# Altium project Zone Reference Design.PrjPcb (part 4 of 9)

## Sheet DRV8x45S-Q1 and DRV81242-Q1.SchDoc
size 431 x 279 mm; Date: Not shown in title block; ApprovedBy: Not shown in title block; CheckedBy: Not shown in title block; Author: Not shown in title block; CompanyName: Not shown in title block; Engineer: Not shown in title block; Organization: Not shown in title block; Address1: Not shown in title block; Address2: Not shown in title block; Address3: Not shown in title block; Address4: Not shown in title block; DocumentNumber: 1; Revision: Use project parameter SCH_Rev; SheetNumber: 18; SheetTotal: 30; PageSetup: Record=PageOptions¦CenterHorizontal=True¦CenterVertical=True¦PrintScale=1.00¦XCorrection=1.00¦YCorrection=1.00¦PrintKind=0¦BorderSize=5000000¦LeftOffset=0¦BottomOffset=0¦Orientation=2¦PaperLength=1000¦PaperWidth=1000¦Scale=100¦PaperSource=15¦PrintQuality=600¦MediaType=1¦DitherType=10¦PaperKind=Letter¦PrintScaleMode=1
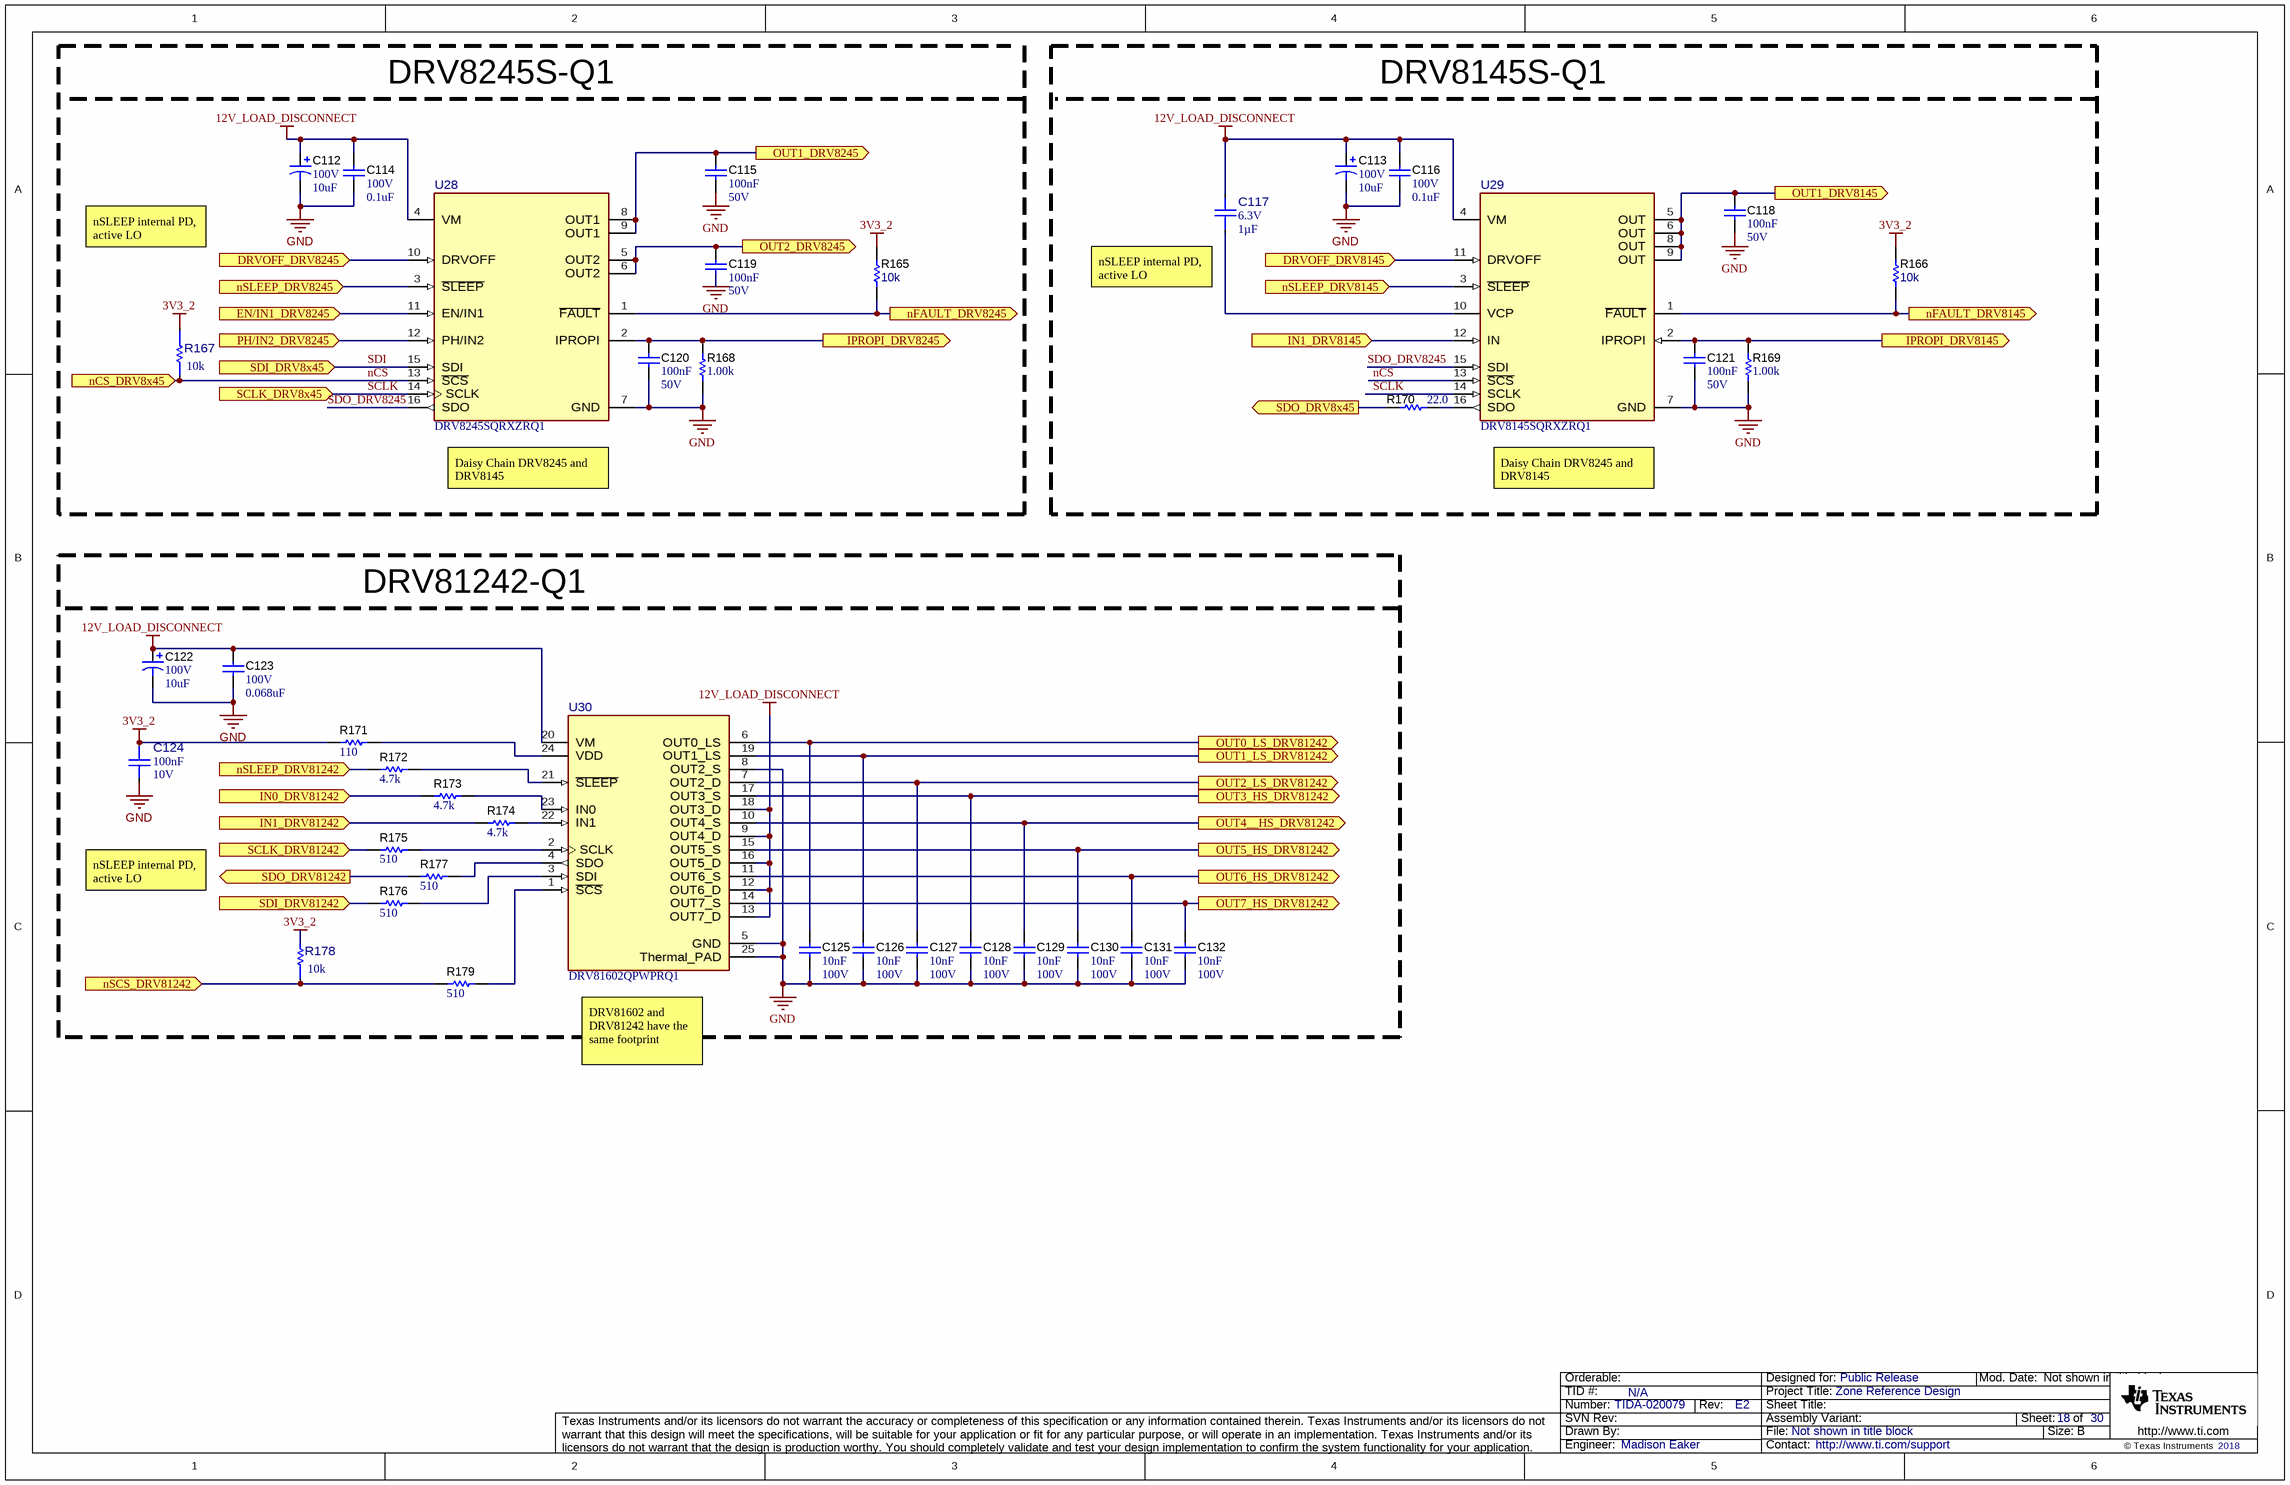
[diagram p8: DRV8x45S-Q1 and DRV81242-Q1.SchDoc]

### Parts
C112  VDC_V: 100V  ValueDisplayed: 10uF  [SM_RADIAL_E]  (hidden comment: EEE-2AA100UP)
C113  VDC_V: 100V  ValueDisplayed: 10uF  [SM_RADIAL_E]  (hidden comment: EEE-2AA100UP)
C114  VDC_V: 100V  ValueDisplayed: 0.1uF  [1206_180]  (hidden comment: C3216X7R2A104K160AA)
C115  Cap_F: 100nF  VDC_V: 50V  [0603]  (hidden comment: 885012206095)
C116  VDC_V: 100V  ValueDisplayed: 0.1uF  [1206_180]  (hidden comment: C3216X7R2A104K160AA)
C117  VDC_V: 6.3V  Cap_F: 1µF  [FP-C0603X105J9RACAUTO_0603-MFG]  (hidden comment: C0603X105J9RACAUTO)
C118  Cap_F: 100nF  VDC_V: 50V  [0603]  (hidden comment: 885012206095)
C119  Cap_F: 100nF  VDC_V: 50V  [0603]  (hidden comment: 885012206095)
C120  Cap_F: 100nF  VDC_V: 50V  [0603]  (hidden comment: 885012206095)
C121  Cap_F: 100nF  VDC_V: 50V  [0603]  (hidden comment: 885012206095)
C122  VDC_V: 100V  ValueDisplayed: 10uF  [SM_RADIAL_E]  (hidden comment: EEE-2AA100UP)
C123  VDC_V: 100V  ValueDisplayed: 0.068uF  [0603]  (hidden comment: CGA3E3X7S2A683K080AB)
C124  value 100nF  VDC_V: 10V  [FP-885012205018_0402-MFG]  (hidden comment: 885012205018)
C125  Cap_F: 10nF  VDC_V: 100V  [0603]  (hidden comment: CGA3E2X7R2A103K080AA)
C126  Cap_F: 10nF  VDC_V: 100V  [0603]  (hidden comment: CGA3E2X7R2A103K080AA)
C127  Cap_F: 10nF  VDC_V: 100V  [0603]  (hidden comment: CGA3E2X7R2A103K080AA)
C128  Cap_F: 10nF  VDC_V: 100V  [0603]  (hidden comment: CGA3E2X7R2A103K080AA)
C129  Cap_F: 10nF  VDC_V: 100V  [0603]  (hidden comment: CGA3E2X7R2A103K080AA)
C130  Cap_F: 10nF  VDC_V: 100V  [0603]  (hidden comment: CGA3E2X7R2A103K080AA)
C131  Cap_F: 10nF  VDC_V: 100V  [0603]  (hidden comment: CGA3E2X7R2A103K080AA)
C132  Cap_F: 10nF  VDC_V: 100V  [0603]  (hidden comment: CGA3E2X7R2A103K080AA)
R165  ValueDisplayed: 10k  [0603]  (hidden comment: RC0603JR-0710KL)
R166  ValueDisplayed: 10k  [0603]  (hidden comment: RC0603JR-0710KL)
R167  value 10k  [FP-RC0402JR-0710KL_0402-MFG]  (hidden comment: RC0402JR-0710KL)
R168  ValueDisplayed: 1.00k  [0603]  (hidden comment: CRCW06031K00FKEA)
R169  ValueDisplayed: 1.00k  [0603]  (hidden comment: CRCW06031K00FKEA)
R170  ValueDisplayed: 22.0  [0201]  (hidden comment: RC0201FR-0722RL)
R171  ValueDisplayed: 110  [0603]  (hidden comment: CRCW0603110RJNEA)
R172  ValueDisplayed: 4.7k  [0603]  (hidden comment: CRCW06034K70JNEA)
R173  ValueDisplayed: 4.7k  [0603]  (hidden comment: CRCW06034K70JNEA)
R174  ValueDisplayed: 4.7k  [0603]  (hidden comment: CRCW06034K70JNEA)
R175  ValueDisplayed: 510  [0603]  (hidden comment: CRCW0603510RJNEA)
R176  ValueDisplayed: 510  [0603]  (hidden comment: CRCW0603510RJNEA)
R177  ValueDisplayed: 510  [0603]  (hidden comment: CRCW0603510RJNEA)
R178  value 10k  [FP-RC0402JR-0710KL_0402-MFG]  (hidden comment: RC0402JR-0710KL)
R179  ValueDisplayed: 510  [0603]  (hidden comment: CRCW0603510RJNEA)
U28  DRV8245SQRXZRQ1  [RXZ0016A-MFG]
U29  DRV8145SQRXZRQ1  [RXZ0016A-MFG]
U30  DRV81602QPWPRQ1  [PWP0024T-MFG]

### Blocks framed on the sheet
DRV8145S-Q1: C113 C116-C118 C121 R166 R169 R170 U29

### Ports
DRVOFF_DRV8145 (in), DRVOFF_DRV8245 (in), EN/IN1_DRV8245 (in), IN0_DRV81242 (in), IN1_DRV8145 (in), IN1_DRV81242 (in), IPROPI_DRV8145 (out), IPROPI_DRV8245 (out), nCS_DRV8x45 (in), nFAULT_DRV8145 (out), nFAULT_DRV8245 (out), nSCS_DRV81242 (in), nSLEEP_DRV8145 (in), nSLEEP_DRV8245 (in), nSLEEP_DRV81242 (in), OUT0_LS_DRV81242 (out), OUT1_DRV8145 (out), OUT1_DRV8245 (out), OUT1_LS_DRV81242 (out), OUT2_DRV8245 (out), OUT2_LS_DRV81242 (out), OUT3_HS_DRV81242 (out), OUT4__HS_DRV81242 (out), OUT5_HS_DRV81242 (out), OUT6_HS_DRV81242 (out), OUT7_HS_DRV81242 (out), PH/IN2_DRV8245 (in), SCLK_DRV8x45 (in), SCLK_DRV81242 (in), SDI_DRV8x45 (in), SDI_DRV81242 (in), SDO_DRV8x45 (out), SDO_DRV81242 (out)

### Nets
3V3_2: C124.1 R165.2 R166.2 R167.1 R171.1 R178.1
12V_LOAD_DISCONNECT: C112.1(+) C113.1(+) C114.1 C116.1 C117.2 C122.1(+) C123.1 U28.4(VM) U29.4(VM) U30.9(OUT4_D) U30.12(OUT6_D) U30.13(OUT7_D) U30.16(OUT5_D) U30.18(OUT3_D) U30.20(VM)  [project net VS]
GND: C112.2(-) C113.2(-) C114.2 C115.1 C116.2 C118.1 C119.1 C120.1 C121.1 C122.2(-) C123.2 C124.2 C125.2 C126.2 C127.2 C128.2 C129.2 C130.2 C131.2 C132.2 R168.1 R169.1 U28.7(GND) U29.7(GND) U30.5(GND) U30.8(OUT2_S) U30.25(Thermal_PAD)
ADC4_AIN0: C121.2 R169.2 U29.2(IPROPI) ; port IPROPI_DRV8145
ADC4_AIN1: C120.2 R168.2 U28.2(IPROPI) ; port IPROPI_DRV8245
CS_LD_4: R178.2 R179.1 ; port nSCS_DRV81242
DRVOFF_DRV8145: U28.10(DRVOFF) U29.11(DRVOFF) ; port DRVOFF_DRV8245, port DRVOFF_DRV8145
EN/IN1_DRV8245: U28.11(EN/IN1) ; port EN/IN1_DRV8245
EPWM0_B: U28.12(PH/IN2) ; port PH/IN2_DRV8245
EPWM1_A: R173.1 ; port IN0_DRV81242
EPWM1_B: R174.1 ; port IN1_DRV81242
EPWM2_A: U29.12(IN) ; port IN1_DRV8145
nCS: R167.2 U28.13(~{SCS}) U29.13(~{SCS}) ; port nCS_DRV8x45
nFAULT_DRV8145: R165.1 R166.1 U28.1(~{FAULT}) U29.1(~{FAULT}) ; port nFAULT_DRV8245, port nFAULT_DRV8145
nSLEEP_DRV81242: R172.1 U28.3(~{SLEEP}) U29.3(~{SLEEP}) ; port nSLEEP_DRV8245, port nSLEEP_DRV8145, port nSLEEP_DRV81242
OUT0_LS_DRV81242: C125.1 U30.6(OUT0_LS) ; port OUT0_LS_DRV81242
OUT1_DRV8145: C118.2 U29.5(OUT) U29.6(OUT) U29.8(OUT) U29.9(OUT) ; port OUT1_DRV8145
OUT1_DRV8245: C115.2 U28.8(OUT1) U28.9(OUT1) ; port OUT1_DRV8245
OUT1_LS_DRV81242: C126.1 U30.19(OUT1_LS) ; port OUT1_LS_DRV81242
OUT2_DRV8245: C119.2 U28.5(OUT2) U28.6(OUT2) ; port OUT2_DRV8245
OUT2_LS_DRV81242: C127.1 U30.7(OUT2_D) ; port OUT2_LS_DRV81242
OUT3_HS_DRV81242: C128.1 U30.17(OUT3_S) ; port OUT3_HS_DRV81242
OUT4__HS_DRV81242: C129.1 U30.10(OUT4_S) ; port OUT4__HS_DRV81242
OUT5_HS_DRV81242: C130.1 U30.15(OUT5_S) ; port OUT5_HS_DRV81242
OUT6_HS_DRV81242: C131.1 U30.11(OUT6_S) ; port OUT6_HS_DRV81242
OUT7_HS_DRV81242: C132.1 U30.14(OUT7_S) ; port OUT7_HS_DRV81242
SCLK: R175.1 U28.14(SCLK) U29.14(SCLK) ; port SCLK_DRV8x45, port SCLK_DRV81242
SDI: R176.1 U28.15(SDI) ; port SDI_DRV8x45, port SDI_DRV81242
SDO_DRV8245: U28.16(SDO) U29.15(SDI)  [project net SDO_DRV8245_18]
SDO_LD: R170.1 R177.1 ; port SDO_DRV8x45, port SDO_DRV81242
NetC117_1: C117.1 U29.10(VCP)
NetR170_2: R170.2 U29.16(SDO)
NetR171_2: R171.2 U30.24(VDD)
NetR172_2: R172.2 U30.21(~{SLEEP})
NetR173_2: R173.2 U30.23(IN0)
NetR174_2: R174.2 U30.22(IN1)
NetR175_2: R175.2 U30.2(SCLK)
NetR176_2: R176.2 U30.3(SDI)
NetR177_2: R177.2 U30.4(SDO)
NetR179_2: R179.2 U30.1(~{SCS})

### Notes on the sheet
- DRV8245S-Q1
- nSLEEP internal PD, active LO
- (near C117) nSLEEP internal PD, active LO
- (near U28) Daisy Chain DRV8245 and DRV8145
- (near U29) Daisy Chain DRV8245 and DRV8145
- DRV81242-Q1
- (near U30) DRV81602 and DRV81242 have the same footprint

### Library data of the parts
C112 C113 C122 = CMP-0011164-2: CAP, AL, 10 uF, 100 V, +/- 20%, AEC-Q200 Grade 3, SMD; Manufacturer: Panasonic; TaMin_C: -40°C; Polarized: Y; SizeAreaWB_mm2: 118.45; Value1: Unknown; U/M: EA; Value: 10uF; TaMax_C: 85°C; SizeZ_mm: 6.2; SizeX_mm: 9.5; SizeY_mm: 8.3; Cap_Case: 8.0x6.0mm; SizeArea_mm2: 78.85; CompType: Capacitor; Cap_F: 10µF; IRMS_A: 50mA; AEC Grade: 3; AEC Category: Q200
C114 C116 = CMP-0008709-1: CAP, CERM, 0.1 uF, 100 V, +/- 10%, X7R, 1206; Manufacturer: TDK; TaMin_C: -55°C; ESR_ohm: 0.030343; Polarized: N; SizeAreaWB_mm2: 10.92; Value1: 0.030343 ohm; U/M: EA; Value: 0.1uF; TaMax_C: 125°C; SizeZ_mm: 1.8; SizeX_mm: 3.2; SizeY_mm: 1.6; SizeArea_mm2: 5.12; Cap_F: 100nF; IRMS_A: 1.33802A; AEC Category: Q200
C115 C118-C121 = CMP-0006837-2: CAP, CERM, 0.1 uF, 50 V, +/- 10%, X7R, 0603; Manufacturer: Wurth Elektronik; TaMin_C: -55°C; Polarized: N; SizeAreaWB_mm2: 4.68; Value1: Unknown; U/M: EA; Value: 0.1uF; TaMax_C: 125°C; SizeZ_mm: 1; SizeX_mm: 1.6; SizeY_mm: 0.8; SizeArea_mm2: 1.28; AEC Category: Q200
C117 = CMP-0095056-1: Cap Ceramic 1uF 6.3V X7R 5% Pad SMD 0603 Flexible Termination 125°C Automotive T/R; Manufacturer: KEMET; AEC Grade: Grade 1; Value: 1µF; SizeZ_mm: 0.95mm; AEC Qualified: Yes; TempCo: 15%
C123 = CMP-0007102-3: CAP, CERM, 0.068 uF, 100 V, +/- 10%, X7S, AEC-Q200 Grade 1, 0603; Manufacturer: TDK; TaMin_C: -55°C; ESR_ohm: 74.084m; Polarized: N; SizeAreaWB_mm2: 4.68; Value1: 0.074084 ohm; U/M: EA; TaMax_C: 125°C; SizeZ_mm: 1; SizeX_mm: 1.6; SizeY_mm: 0.8; SizeArea_mm2: 1.28; AEC Qualified: Y; Cap_F: 68nF; IRMS_A: 619.09mA; AEC Category: Q200
C124 = CMP-0090362-1: 0.1µF ±10% 10V Ceramic Capacitor X7R 0402 (1005 Metric); Manufacturer: Wurth Electronics; AEC Qualified: No; SizeZ_mm: 0.55mm; ValueDisplayed: 100000pF; TempCo: 15%
C125-C132 = CMP-0007082-1: CAP, CERM, 0.01 uF, 100 V, +/- 10%, X7R, AEC-Q200 Grade 1, 0603; Manufacturer: TDK; TaMin_C: -55°C; ESR_ohm: 0.2354; Polarized: N; SizeAreaWB_mm2: 4.68; Value1: 0.235428 ohm; U/M: EA; Value: 0.01uF; TaMax_C: 125°C; SizeZ_mm: 1; SizeX_mm: 1.6; SizeY_mm: 0.8; SizeArea_mm2: 1.28; AEC Qualified: Y; IRMS_A: 396.995mA; AEC Category: Q200
R165 R166 = CMP-0025886-3: RES, 10 k, 5%, 0.1 W, 0603; Manufacturer: Yageo America; Power_W: 100mW; TempCo: 100 ppm/C; Value_Code: 10k0; U/M: EA; Value: 10k; EIA_Code: E24; SizeX_mm: 1.6; SizeY_mm: 0.8; SizeZ_mm: 1; Value2: 0.1W; SizeArea_mm2: 1.28; VDC_V: 50V; AEC Category: Q200
R167 R178 = CMP-0094798-1: Res Thick Film 0402 10K Ohm 5% 0.063W(1/16W) ±100ppm/C Pad SMD T/R; Manufacturer: YAGEO; AEC Qualified: No; Category Cd01000Bfc2916C6: Single Components; SizeZ_mm: 0.4mm; VDC_V: 50V; Category 5C6A91606D4187Ad: Resistors; TempCo: 100ppm/°C; Power_W: 63mW; Category 7542B8484461Ae85: Passive Components
R168 R169 = CMP-0022109-5: RES, 1.00 k, 1%, 0.1 W, AEC-Q200 Grade 0, 0603; Manufacturer: Vishay-Dale; Power_W: 100mW; TempCo: 100 ppm/C; Value_Code: 1k00; Value: 1.00k; EIA_Code: E96; Res_ohm: 1k; SizeX_mm: 1.6; SizeY_mm: 0.8; SizeZ_mm: 1; Value2: 0.1W; SizeArea_mm2: 1.28; AEC Qualified: Y; VDC_V: 75V; AEC Category: Q200; AEC Grade: 0
R170 = CMP-0027500-1: RES, 22.0, 1%, 0.05 W, 0201; Manufacturer: Yageo America; Power_W: 50mW; TempCo: 200 ppm/C; Value_Code: 22R0; U/M: EA; Value: 22.0; Res_ohm: 22; SizeX_mm: 0.6; SizeY_mm: 0.3; SizeZ_mm: 0.26; Value2: 0.05W; SizeArea_mm2: 0.18; AEC Qualified: N; VDC_V: 25V; AEC Category: Q200
R171 = CMP-0025706-4: RES, 110, 5%, 0.1 W, AEC-Q200 Grade 0, 0603; Manufacturer: Vishay-Dale; Power_W: 100mW; TempCo: 200 ppm/C; Value_Code: 110R; Value: 110; EIA_Code: E24; SizeX_mm: 1.6; SizeY_mm: 0.8; SizeZ_mm: 1; Value2: 0.1W; SizeArea_mm2: 1.28; AEC Qualified: Y; VDC_V: 75V; AEC Category: Q200; AEC Grade: 0
R172-R174 = CMP-0025817-4: RES, 4.7 k, 5%, 0.1 W, AEC-Q200 Grade 0, 0603; Manufacturer: Vishay-Dale; Power_W: 100mW; TempCo: 200 ppm/C; Value_Code: 4k70; Value: 4.7k; EIA_Code: E24; SizeX_mm: 1.6; SizeY_mm: 0.8; SizeZ_mm: 1; Value2: 0.1W; SizeArea_mm2: 1.28; AEC Qualified: Y; VDC_V: 75V; AEC Category: Q200; AEC Grade: 0
R175-R177 R179 = CMP-0025823-4: RES, 510, 5%, 0.1 W, AEC-Q200 Grade 0, 0603; Manufacturer: Vishay-Dale; Power_W: 100mW; TempCo: 200 ppm/C; Value_Code: 510R; Value: 510; EIA_Code: E24; SizeX_mm: 1.6; SizeY_mm: 0.8; SizeZ_mm: 1; Value2: 0.1W; SizeArea_mm2: 1.28; AEC Qualified: Y; VDC_V: 75V; AEC Category: Q200; AEC Grade: 0
U28 = CMP-0095863-1: Automotive H-Bridge Driver with Integrated Current Sense and Diagnostics; Manufacturer: Texas Instruments; Max Supply Voltage: 35V; Number Of Outputs: 2; Min Supply Voltage: 4.5V; TaMax_C: +125°C; AEC Qualified: Yes; TJmax_C: +150°C; Nominal Supply Current: 10mA; Switching Frequency: 25kHz; Standoff Height: 0mm; SizeZ_mm: 1mm; AEC Grade: Grade 1; TaMin_C: -40°C
U29 = CMP-0096004-1: Automotive Half Bridge Driver with Integrated Current Sense and Diagnostics; Manufacturer: Texas Instruments; AEC Grade: Grade 1; Standoff Height: 0mm; Number Of Outputs: 1; TaMin_C: -40°C; Propagation Delay: 4.2us; TJmax_C: +150°C; Min Supply Voltage: 4.5V; Max Supply Voltage: 35V; AEC Qualified: Yes; TaMax_C: +125°C; Nominal Supply Current: 10mA; SizeZ_mm: 1mm
U30 = CMP-0122276-1: 8-channel Configurable Low-side and High-side Driver for Automotive Relay, Lighting and Motor Control; Manufacturer: Texas Instruments; SizeZ_mm: 1.2mm; AEC Qualified: No; Max Supply Voltage: 40V; Min Supply Voltage: 3V; Nominal Supply Current: 2.6-4.5mA; Number Of Drivers: 8; Standoff Height: 0.05mm; TaMax_C: +125°C; TaMin_C: -40°C; TJmax_C: +150°C; Turn Off Delay Time: 8.5us; Turn On Delay Time: 5.5us

## Sheet TPS1211-Q1.SchDoc
size 431 x 279 mm; Date: Not shown in title block; ApprovedBy: Not shown in title block; CheckedBy: Not shown in title block; Author: Not shown in title block; CompanyName: Not shown in title block; Engineer: Not shown in title block; Organization: Not shown in title block; Address1: Not shown in title block; Address2: Not shown in title block; Address3: Not shown in title block; Address4: Not shown in title block; DocumentNumber: 1; Revision: Use project parameter SCH_Rev; SheetNumber: 14; SheetTotal: 30; PageSetup: Record=PageOptions¦CenterHorizontal=True¦CenterVertical=True¦PrintScale=1.00¦XCorrection=1.00¦YCorrection=1.00¦PrintKind=0¦BorderSize=5000000¦LeftOffset=0¦BottomOffset=0¦Orientation=2¦PaperLength=1000¦PaperWidth=1000¦Scale=100¦PaperSource=15¦PrintQuality=600¦MediaType=1¦DitherType=10¦PaperKind=Letter¦PrintScaleMode=1
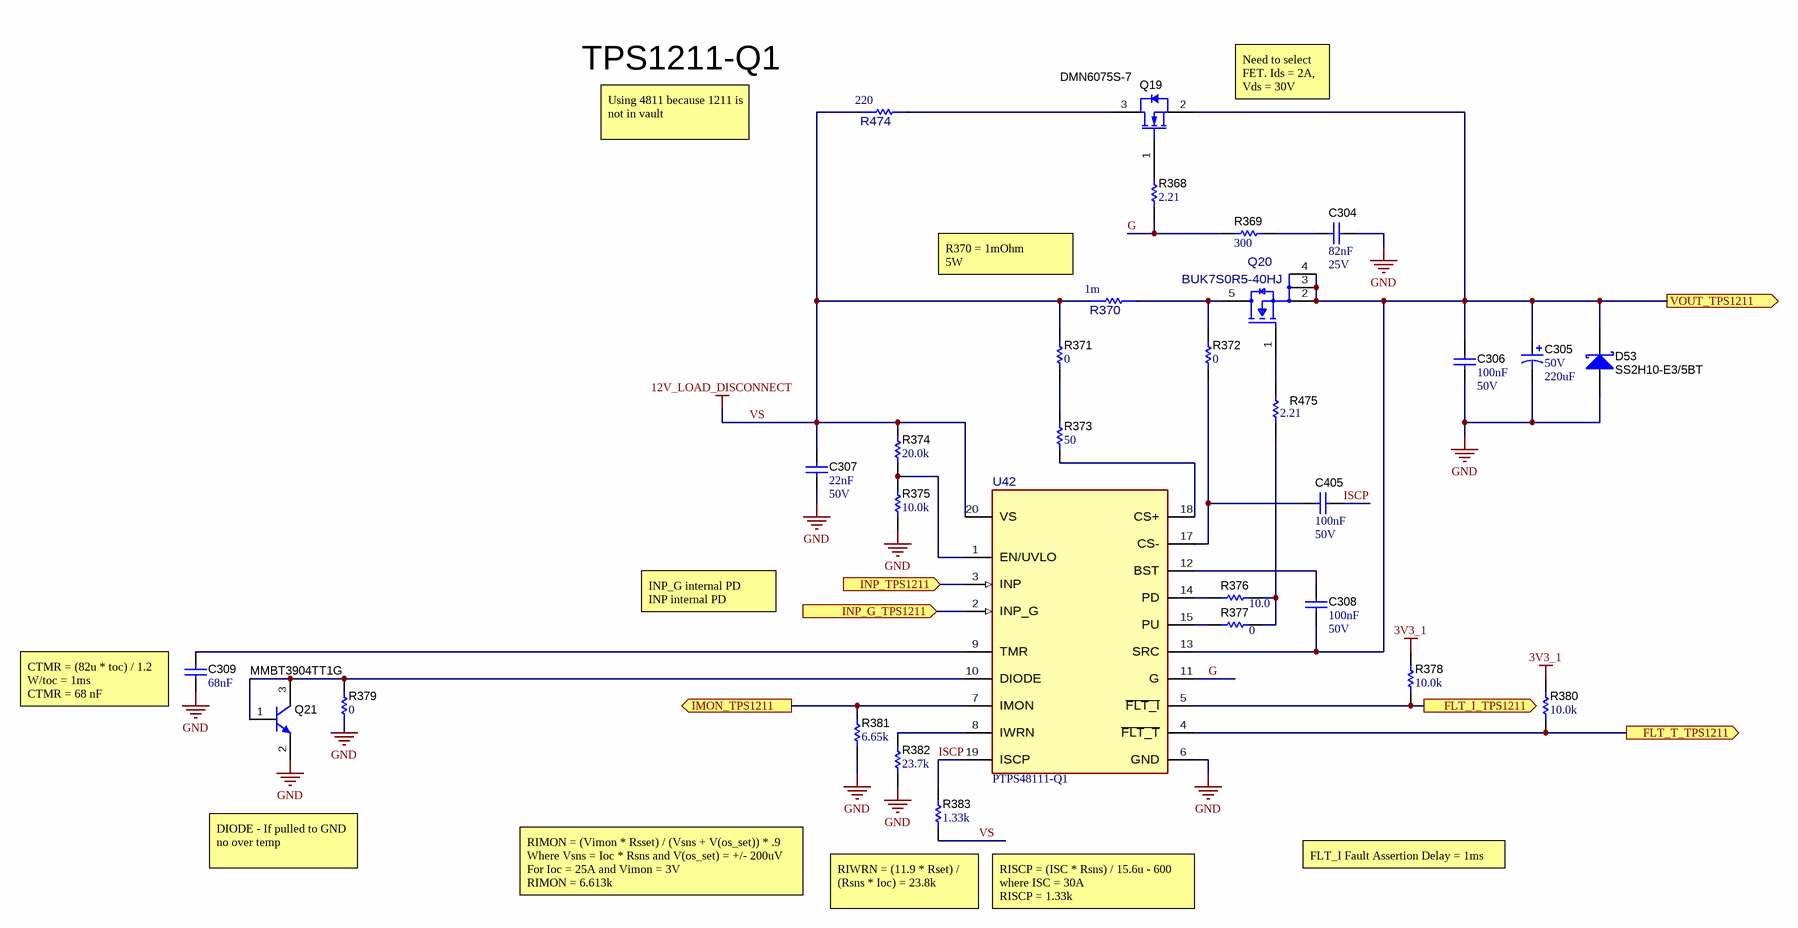
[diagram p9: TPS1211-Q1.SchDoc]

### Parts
C304  Cap_F: 82nF  VDC_V: 25V  [0603]  (hidden comment: GRM188R71E823KA01D)
C305  VDC_V: 50V  ValueDisplayed: 220uF  [SM_RADIAL_G]  (hidden comment: EEVFK1H221P)
C306  Cap_F: 100nF  VDC_V: 50V  [0603]  (hidden comment: CGA3E2X7R1H104K080AA)
C307  Cap_F: 22nF  VDC_V: 50V  [0603]  (hidden comment: C0603C223K5RACTU)
C308  Cap_F: 100nF  VDC_V: 50V  [0603]  (hidden comment: 06035C104KAZ2A)
C309  Cap_F: 68nF  [0603]  (hidden comment: 06035C104KAZ2A)
C405  Cap_F: 100nF  VDC_V: 50V  [0603]  (hidden comment: 06035C104KAZ2A)
D53  SS2H10-E3/5BT  [SMB]
Q19  DMN6075S-7  [SOT-23]
Q20  BUK7S0R5-40HJ  [FP-BUK7S0R5-40HJ_SOT1235-MFG]
Q21  MMBT3904TT1G  [SOT-416]
R368  ValueDisplayed: 2.21  [0603]  (hidden comment: RT0603DRE072R21L)
R369  ValueDisplayed: 300  [0603]  (hidden comment: RC0603FR-07300RL)
R370  Res_ohm: 1m  [FP-WSLF25121L000FEB_2512-MFG]  (hidden comment: WSLF25121L000FEB)
R371  ValueDisplayed: 0  [0603]  (hidden comment: CRCW06030000Z0EA)
R372  ValueDisplayed: 0  [0603]  (hidden comment: CRCW06030000Z0EA)
R373  ValueDisplayed: 50  [0603]  (hidden comment: CRCW060350R0FKEA)
R374  ValueDisplayed: 20.0k  [0603]  (hidden comment: ERJ-3EKF2002V)
R375  ValueDisplayed: 10.0k  [0603]  (hidden comment: ERJ-3EKF1002V)
R376  ValueDisplayed: 10.0  [0603]  (hidden comment: TNPW060310R0BEEA)
R377  ValueDisplayed: 0  [0603]  (hidden comment: CRCW06030000Z0EA)
R378  ValueDisplayed: 10.0k  [0603]  (hidden comment: ERJ-3EKF1002V)
R379  ValueDisplayed: 0  [0603]  (hidden comment: CRCW06030000Z0EA)
R380  ValueDisplayed: 10.0k  [0603]  (hidden comment: ERJ-3EKF1002V)
R381  ValueDisplayed: 6.65k  [0603]  (hidden comment: RC0603FR-076K65L)
R382  ValueDisplayed: 23.7k  [0603]  (hidden comment: RC0603FR-0723K7L)
R383  ValueDisplayed: 1.33k  [0603]  (hidden comment: RC0603FR-071K33L)
R474  Res_ohm: 220  [FP-3502220RFT_2010-MFG]  (hidden comment: 3502220RFT)
R475  ValueDisplayed: 2.21  [0603]  (hidden comment: RT0603DRE072R21L)
U42  PTPS48111-Q1  [0-MFG]

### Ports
FLT_I_TPS1211 (out), FLT_T_TPS1211 (out), IMON_TPS1211 (out), INP_G_TPS1211 (in), INP_TPS1211 (in), VOUT_TPS1211 (out)

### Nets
3V3_1: R378.1 R380.1
GND: C304.1 C305.2(-) C306.2 C307.1 C309.2 D53.2(A) Q21.2(E) R375.2 R379.1 R381.1 R382.1 U42.6(GND)
VS: C307.2 R370.1 R371.2 R374.2 R383.1 R474.1 U42.20(VS)  [also labelled 12V_LOAD_DISCONNECT]
ADC2_AIN5: R381.2 U42.7(IMON) ; port IMON_TPS1211
FLT_I_TPS1211: R378.2 U42.5(~{FLT_I}) ; port FLT_I_TPS1211
FLT_T_TPS1211: R380.2 U42.4(~{FLT_T}) ; port FLT_T_TPS1211
G: R368.1 R369.1 U42.11(G)  [project net G_14]
INP_G_TPS1211: U42.2(INP_G) ; port INP_G_TPS1211
INP_TPS1211: U42.3(INP) ; port INP_TPS1211
ISCP: C405.1 R383.2 U42.19(ISCP)  [project net ISCP_14]
VOUT_TPS1211: C305.1(+) C306.1 C308.1 D53.1(K) Q19.2(S) Q20.2(S) Q20.3(S) Q20.4(S) U42.13(SRC) ; port VOUT_TPS1211
NetC304_2: C304.2 R369.2
NetC308_2: C308.2 U42.12(BST)
NetC309_1: C309.1 U42.9(TMR)
NetC405_2: C405.2 R372.1 U42.17(CS-)
NetQ19_1: Q19.1(G) R368.2
NetQ19_3: Q19.3(D) R474.2
NetQ20_1: Q20.1(G) R475.2
NetQ20_5: Q20.5(D) R370.2 R372.2
NetQ21_1: Q21.1(B) Q21.3(C) R379.2 U42.10(DIODE)
NetR371_1: R371.1 R373.1
NetR373_2: R373.2 U42.18(CS+)
NetR374_1: R374.1 R375.1 U42.1(EN/UVLO)
NetR376_1: R376.1 R377.1 R475.1
NetR376_2: R376.2 U42.14(PD)
NetR377_2: R377.2 U42.15(PU)
NetR382_2: R382.2 U42.8(IWRN)

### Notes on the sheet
- TPS1211-Q1
- Using 4811 because 1211 is not in vault
- Need to select FET. Ids = 2A, Vds = 30V
- (near R370) R370 = 1mOhm
  5W
- INP_G internal PD
  INP internal PD
- (near C309) CTMR = (82u * toc) / 1.2 W/toc = 1ms                               CTMR = 68 nF
- DIODE - If pulled to GND no over temp
- RIMON = (Vimon * Rsset) / (Vsns + V(os_set)) * .9                     Where Vsns = Ioc * Rsns and V(os_set) = +/- 200uV                For Ioc = 25A and Vimon = 3V                           RIMON = 6.613k
- FLT_I Fault Assertion Delay = 1ms
- (near R383) RIWRN = (11.9 * Rset) / (Rsns * Ioc) = 23.8k
- RISCP = (ISC * Rsns) / 15.6u - 600                        where ISC = 30A                                   RISCP = 1.33k

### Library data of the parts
C304 = CMP-0007430-2: CAP, CERM, 0.082 uF, 25 V, +/- 10%, X7R, 0603; Manufacturer: MuRata; TaMin_C: -55°C; Polarized: N; SizeAreaWB_mm2: 4.68; Value1: Unknown; U/M: EA; TaMax_C: 125°C; SizeZ_mm: 1; SizeX_mm: 1.6; SizeY_mm: 0.8; SizeArea_mm2: 1.28; AEC Category: Q200
C305 = CMP-0011210-2: CAP, AL, 220 uF, 50 V, +/- 20%, 0.1 ohm, AEC-Q200 Grade 2, SMD; Manufacturer: Panasonic; TaMin_C: -55°C; ESR_ohm: 0.1; Polarized: Y; SizeAreaWB_mm2: 172.2; Value1: 0.1 ohm; U/M: EA; Value: 220uF; TaMax_C: 125°C; SizeZ_mm: 10.2; SizeX_mm: 12; SizeY_mm: 10.3; Cap_Case: G; SizeArea_mm2: 123.6; CompType: Capacitor; Cap_F: 220µF; AEC Grade: 2; AEC Category: Q200
C306 = CMP-0007078-1: CAP, CERM, 0.1 uF, 50 V, +/- 10%, X7R, AEC-Q200 Grade 1, 0603; Manufacturer: TDK; TaMin_C: -55°C; ESR_ohm: 29.6m; Polarized: N; SizeAreaWB_mm2: 4.68; Value1: 0.0296 ohm; U/M: EA; Value: 0.1uF; TaMax_C: 125°C; SizeZ_mm: 1; SizeX_mm: 1.6; SizeY_mm: 0.8; SizeArea_mm2: 1.28; AEC Qualified: Y; IRMS_A: 971.99mA; AEC Category: Q200
C307 = CMP-0006901-3: CAP, CERM, 0.022 uF, 50 V, +/- 10%, X7R, 0603; Manufacturer: Kemet; TaMin_C: -55°C; Polarized: N; Value1: Unknown; U/M: EA; TaMax_C: 125°C; SizeAreaWB_mm2: 4.68; SizeZ_mm: 1; SizeX_mm: 1.6; SizeY_mm: 0.8; SizeArea_mm2: 1.28; AEC Category: Q200
C308 C405 = CMP-0079095-1: CAP, CERM, 0.1 µF, 50 V,+/- 10%, X7R, AEC-Q200 Grade 1, 0603; Manufacturer: AVX; SizeAreaWB_mm2: 4.68; SizeArea_mm2: 1.28; AEC Qualified: Y; AEC Category: Q200; Value: 0.1uF; TaMax_C: 125°C; SizeZ_mm: 1; Polarized: N; TaMin_C: -55°C; SizeY_mm: 0.8; U/M: EA; SizeX_mm: 1.6; ValueDisplayed: 0.1µF
C309 = CMP-0079095-1: CAP, CERM, 0.1 µF, 50 V,+/- 10%, X7R, AEC-Q200 Grade 1, 0603; Manufacturer: AVX; SizeAreaWB_mm2: 4.68; SizeArea_mm2: 1.28; AEC Qualified: Y; AEC Category: Q200; Value: 0.1uF; TaMax_C: 125°C; SizeZ_mm: 1; Polarized: N; TaMin_C: -55°C; VDC_V: 50V; SizeY_mm: 0.8; U/M: EA; SizeX_mm: 1.6; ValueDisplayed: 0.1µF
D53 = CMP-0028987-2: Diode, Schottky, 100 V, 2 A, SMB; Manufacturer: Vishay-Semiconductor; Vf_V: 790mV; AEC Qualified: N; SizeArea_mm2: 21.336; Value: 100V; SizeX_mm: 5.6; Value1: 2A; Value2: 0.79V; SizeZ_mm: 2.6; SizeAreaWB_mm2: 44.156; AEC Category: Q101; TJmax_C: 175°C; SizeY_mm: 3.81
Q19 = CMP-0078323-1: MOSFET, N-CH, 60 V, 2 A, AEC-Q101, SOT-23; Manufacturer: Diodes Inc.; Alternate Manufacturer: None; ChType: N; QgTyp_nC: 5.6; SizeAreaWB_mm2: 14; SizeArea_mm2: 7.5; IdsMax_A: 2A; AEC Qualified: Y; VdsMax_V: 60V; Rdson45_ohm: 0.12; Vgs_V: 20V; AEC Category: Q101; Value: 60V; SizeZ_mm: 1.1; SizeY_mm: 3; Value2: 5.6 nC; U/M: EA; Value1: 0.12 ohm; SizeX_mm: 2.5
Q20 = CMP-0095948-1: N-Channel 40 V 500A (Ta) 375W (Ta) Surface Mount LFPAK88 (SOT1235); Manufacturer: Nexperia; Number Of Channels: 1; Threshold Vgs Max: 3.6V; Rdson45_ohm: 470µ; ChMode: False; Turn On Delay Time: 40ns; VdsMax_V: 1V; Input Capacitace At Vds: 15116pF @ 25V; Reverse Recovery Time: 62ns; QgTyp_nC: 190nC @ 10V; Reverse Recovery Charge: 93nC; AEC Grade: Grade 0; AEC Qualified: Yes; TJmax_C: +175°C; Typ Forward Diode Voltage: 0.79V; Pulse Drain Current: 2237A; SizeZ_mm: 1.85mm; Standoff Height: 0mm; Drain To Source Breakdown Voltage: 43V; Vgs_V: 20V; Threshold Vgs Min: 2.4V; Turn Off Delay Time: 117ns
Q21 = CMP-0000428-2: Transistor, NPN, 40 V, 0.2 A, SOT-416; Manufacturer: ON Semiconductor; TaMax_C: 150°C; Value2: 300; Value1: 0.2 A; Vcesat1_V: 300mV; SizeX_mm: 1.6; TaMin_C: -55°C; IcRated_A: 200mA; CompType: BJT; SizeZ_mm: 0.95; Value: 40 V; SizeArea_mm2: 2.56; NPN: 1; Vceo_V: 40V; PNP: 0; AEC Category: Q101; SizeAreaWB_mm2: 6.76; U/M: EA
R368 R475 = CMP-0025088-1: RES, 2.21, 0.5%, 0.1 W, 0603; Manufacturer: Yageo America; Power_W: 100mW; TempCo: 50 ppm/C; Value_Code: 2R21; U/M: EA; Value: 2.21; EIA_Code: E192; SizeX_mm: 1.6; SizeY_mm: 0.8; SizeZ_mm: 1; Value2: 0.1W; SizeArea_mm2: 1.28; VDC_V: 75V; AEC Category: Q200
R369 = CMP-0023013-5: RES, 300, 1%, 0.1 W, 0603; Manufacturer: Yageo; Power_W: 100mW; TempCo: 100 ppm/C; Value_Code: 300R; Value: 300; SizeX_mm: 1.6; SizeY_mm: 0.8; SizeZ_mm: 1; Value2: 0.1W; SizeArea_mm2: 1.28; AEC Qualified: N; VDC_V: 75V; AEC Category: Q200; SizeAreaWB_mm2: 4.68
R370 = CMP-0089827-1: 1 mOhms ±1% 5W Chip Resistor 2512 (6432 Metric) Automotive AEC-Q200, Current Sense, Moisture Resistant, Pulse Withstanding Metal Element; Manufacturer: Vishay; SizeZ_mm: 0.81mm; AEC Grade: Grade 0; Standoff Height: 0.32mm; AEC Qualified: Yes; TempCo: 170ppm/°C
R371 R372 R377 R379 = CMP-0025697-4: RES, 0, 5%, 0.1 W, AEC-Q200 Grade 0, 0603; Manufacturer: Vishay-Dale; Power_W: 100mW; TempCo: 200 ppm/C; Value_Code: 0000; Value: 0; EIA_Code: E24; SizeX_mm: 1.6; SizeY_mm: 0.8; SizeZ_mm: 1; Value2: 0.1W; SizeArea_mm2: 1.28; CompType: Resistor; AEC Qualified: Y; VDC_V: 75V; AEC Category: Q200
R373 = CMP-0022479-2: RES, 50, 1%, 0.1 W, 0603; Manufacturer: Vishay-Dale; Power_W: 100mW; TempCo: 100 ppm/C; Value_Code: 50R0; U/M: EA; Value: 50; SizeX_mm: 1.6; SizeY_mm: 0.8; SizeZ_mm: 1; Value2: 0.1W; SizeArea_mm2: 1.28; VDC_V: 75V; AEC Category: Q200
R374 = CMP-0022691-1: RES, 20.0 k, 1%, 0.1 W, AEC-Q200 Grade 0, 0603; Manufacturer: Panasonic; Power_W: 100mW; TempCo: 100 ppm/C; Value_Code: 20k0; U/M: EA; Value: 20.0k; Res_ohm: 20k; SizeX_mm: 1.6; SizeY_mm: 0.8; SizeZ_mm: 1; Value2: 0.1W; SizeArea_mm2: 1.28; AEC Qualified: Y; VDC_V: 75V; AEC Grade: 0; AEC Category: Q200; EIA_Code: E96
R375 R378 R380 = CMP-0022684-3: RES, 10.0 k, 1%, 0.1 W, 0603; Manufacturer: Panasonic; Power_W: 100mW; TempCo: 100 ppm/C; Value_Code: 10k0; U/M: EA; Value: 10.0k; EIA_Code: E96; Res_ohm: 10k; SizeX_mm: 1.6; SizeY_mm: 0.8; SizeZ_mm: 1; Value2: 0.1W; SizeArea_mm2: 1.28; VDC_V: 75V; AEC Category: Q200
R376 = CMP-0025687-2: RES, 10.0, 0.1%, 0.1 W, 0603; Manufacturer: Vishay-Dale; Power_W: 100mW; TempCo: 25 ppm/C; Value_Code: 10R0; U/M: EA; Value: 10.0; EIA_Code: E192; Res_ohm: 10; SizeX_mm: 1.6; SizeY_mm: 0.8; SizeZ_mm: 1; Value2: 0.1W; SizeArea_mm2: 1.28; VDC_V: 75V; AEC Category: Q200
R381 = CMP-0023251-5: RES, 6.65 k, 1%, 0.1 W, 0603; Manufacturer: Yageo; Power_W: 100mW; TempCo: 100 ppm/C; Value_Code: 6k65; Value: 6.65k; EIA_Code: E96; SizeX_mm: 1.6; SizeY_mm: 0.8; SizeZ_mm: 1; Value2: 0.1W; SizeArea_mm2: 1.28; AEC Qualified: N; VDC_V: 75V; AEC Category: Q200; SizeAreaWB_mm2: 4.68
R382 = CMP-0022934-5: RES, 23.7 k, 1%, 0.1 W, 0603; Manufacturer: Yageo; Power_W: 100mW; TempCo: 100 ppm/C; Value_Code: 23k7; Value: 23.7k; EIA_Code: E96; SizeX_mm: 1.6; SizeY_mm: 0.8; SizeZ_mm: 1; Value2: 0.1W; SizeArea_mm2: 1.28; AEC Qualified: N; VDC_V: 75V; AEC Category: Q200; SizeAreaWB_mm2: 4.68
R383 = CMP-0022875-5: RES, 1.33 k, 1%, 0.1 W, 0603; Manufacturer: Yageo; Power_W: 100mW; TempCo: 100 ppm/C; Value_Code: 1k33; Value: 1.33k; EIA_Code: E96; SizeX_mm: 1.6; SizeY_mm: 0.8; SizeZ_mm: 1; Value2: 0.1W; SizeArea_mm2: 1.28; AEC Qualified: N; VDC_V: 75V; AEC Category: Q200; SizeAreaWB_mm2: 4.68
R474 = CMP-0088875-1: 220 Ohms ±1% 2W Chip Resistor 2010 (5025 Metric)  Thick Film; Manufacturer: TE; VDC_V: 200V; TempCo: 100ppm/°C; SizeZ_mm: 1.2mm; AEC Qualified: No
U42 = CMP-0092088-1: 100V Smart High Side controller with Protection and Diagnostics; Manufacturer: Texas Instruments; SizeZ_mm: 1.1mm; Max Supply Voltage: 80V; Standoff Height: 0.05mm; Number Of Outputs: 1; Nominal Supply Current: 1uA; AEC Qualified: Yes; Min Supply Voltage: 3.5V

## Sheet Smart Fuse HSS.SchDoc
size 431 x 279 mm; Date: Not shown in title block; ApprovedBy: Not shown in title block; CheckedBy: Not shown in title block; Author: Not shown in title block; CompanyName: Not shown in title block; Engineer: Not shown in title block; Organization: Not shown in title block; Address1: Not shown in title block; Address2: Not shown in title block; Address3: Not shown in title block; Address4: Not shown in title block; DocumentNumber: 1; Revision: Use project parameter SCH_Rev; SheetNumber: 15; SheetTotal: 30; PageSetup: Record=PageOptions¦CenterHorizontal=True¦CenterVertical=True¦PrintScale=1.00¦XCorrection=1.00¦YCorrection=1.00¦PrintKind=0¦BorderSize=5000000¦LeftOffset=0¦BottomOffset=0¦Orientation=2¦PaperLength=1000¦PaperWidth=1000¦Scale=100¦PaperSource=15¦PrintQuality=600¦MediaType=1¦DitherType=10¦PaperKind=Letter¦PrintScaleMode=1
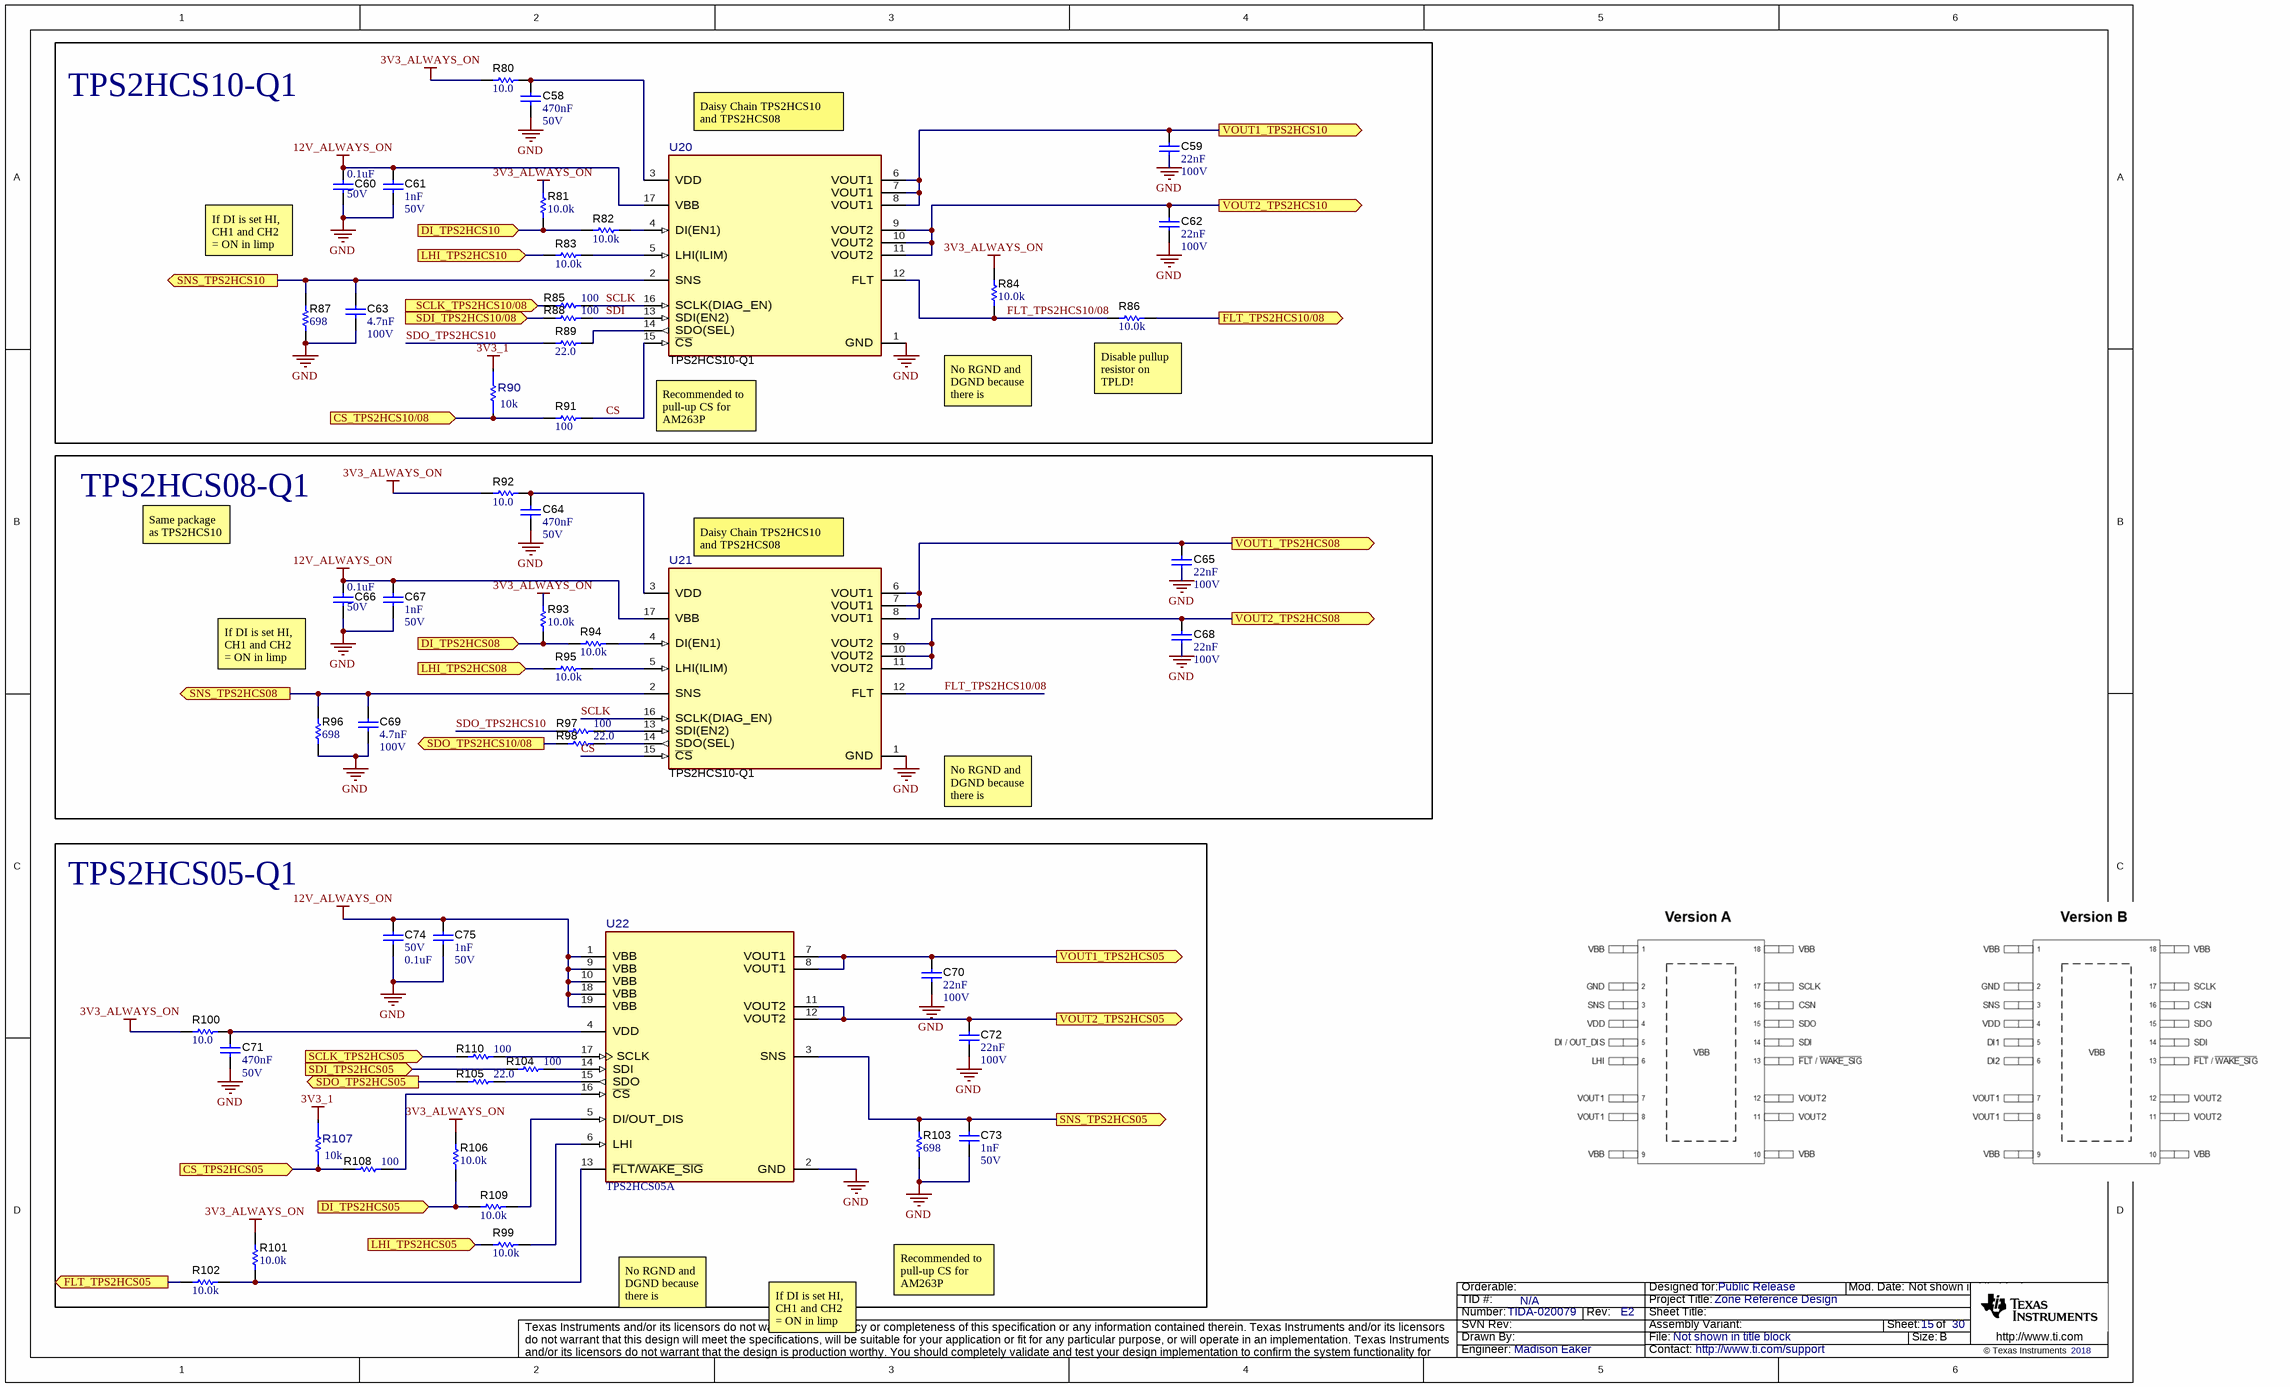
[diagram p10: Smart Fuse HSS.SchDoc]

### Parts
C58  Cap_F: 470nF  VDC_V: 50V  [0603]  (hidden comment: C1608X7R1H474K080AC)
C59  Cap_F: 22nF  VDC_V: 100V  [0603]  (hidden comment: CGA3E2X7R2A223K080AA)
C60  VDC_V: 50V  ValueDisplayed: 0.1uF  [0402]  (hidden comment: GCM155R71H104KE02D)
C61  Cap_F: 1nF  VDC_V: 50V  [0603]  (hidden comment: C0603X102K5RACTU)
C62  Cap_F: 22nF  VDC_V: 100V  [0603]  (hidden comment: CGA3E2X7R2A223K080AA)
C63  Cap_F: 4.7nF  VDC_V: 100V  [0603]  (hidden comment: GCM188R72A472KA37D)
C64  Cap_F: 470nF  VDC_V: 50V  [0603]  (hidden comment: C1608X7R1H474K080AC)
C65  Cap_F: 22nF  VDC_V: 100V  [0603]  (hidden comment: CGA3E2X7R2A223K080AA)
C66  VDC_V: 50V  ValueDisplayed: 0.1uF  [0402]  (hidden comment: GCM155R71H104KE02D)
C67  Cap_F: 1nF  VDC_V: 50V  [0603]  (hidden comment: C0603X102K5RACTU)
C68  Cap_F: 22nF  VDC_V: 100V  [0603]  (hidden comment: CGA3E2X7R2A223K080AA)
C69  Cap_F: 4.7nF  VDC_V: 100V  [0603]  (hidden comment: GCM188R72A472KA37D)
C70  Cap_F: 22nF  VDC_V: 100V  [0603]  (hidden comment: CGA3E2X7R2A223K080AA)
C71  Cap_F: 470nF  VDC_V: 50V  [0603]  (hidden comment: C1608X7R1H474K080AC)
C72  Cap_F: 22nF  VDC_V: 100V  [0603]  (hidden comment: CGA3E2X7R2A223K080AA)
C73  Cap_F: 1nF  VDC_V: 50V  [0603]  (hidden comment: C0603C102K5RACTU)
C74  VDC_V: 50V  ValueDisplayed: 0.1uF  [0402]  (hidden comment: GCM155R71H104KE02D)
C75  Cap_F: 1nF  VDC_V: 50V  [0603]  (hidden comment: C0603X102K5RACTU)
R80  ValueDisplayed: 10.0  [0603]  (hidden comment: CRCW060310R0FKEAHP)
R81  ValueDisplayed: 10.0k  [0603]  (hidden comment: RMCF0603FT10K0)
R82  ValueDisplayed: 10.0k  [0603]  (hidden comment: RMCF0603FT10K0)
R83  ValueDisplayed: 10.0k  [0603]  (hidden comment: RMCF0603FT10K0)
R84  ValueDisplayed: 10.0k  [0603]  (hidden comment: RMCF0603FT10K0)
R85  ValueDisplayed: 100  [0603]  (hidden comment: CRCW0603100RJNEA)
R86  ValueDisplayed: 10.0k  [0603]  (hidden comment: RMCF0603FT10K0)
R87  ValueDisplayed: 698  [0603]  (hidden comment: CRCW0603698RFKEA)
R88  ValueDisplayed: 100  [0603]  (hidden comment: CRCW0603100RJNEA)
R89  ValueDisplayed: 22.0  [0603]  (hidden comment: RC0603FR-0722RL)
R90  value 10k  [FP-RC0402JR-0710KL_0402-MFG]  (hidden comment: RC0402JR-0710KL)
R91  ValueDisplayed: 100  [0603]  (hidden comment: CRCW0603100RJNEA)
R92  ValueDisplayed: 10.0  [0603]  (hidden comment: CRCW060310R0FKEAHP)
R93  ValueDisplayed: 10.0k  [0603]  (hidden comment: RMCF0603FT10K0)
R94  ValueDisplayed: 10.0k  [0603]  (hidden comment: RMCF0603FT10K0)
R95  ValueDisplayed: 10.0k  [0603]  (hidden comment: RMCF0603FT10K0)
R96  ValueDisplayed: 698  [0603]  (hidden comment: CRCW0603698RFKEA)
R97  ValueDisplayed: 100  [0603]  (hidden comment: CRCW0603100RJNEA)
R98  ValueDisplayed: 22.0  [0201]  (hidden comment: RC0201FR-0722RL)
R99  ValueDisplayed: 10.0k  [0603]  (hidden comment: RMCF0603FT10K0)
R100  ValueDisplayed: 10.0  [0603]  (hidden comment: CRCW060310R0FKEAHP)
R101  ValueDisplayed: 10.0k  [0603]  (hidden comment: RMCF0603FT10K0)
R102  ValueDisplayed: 10.0k  [0603]  (hidden comment: RMCF0603FT10K0)
R103  ValueDisplayed: 698  [0603]  (hidden comment: CRCW0603698RFKEA)
R104  ValueDisplayed: 100  [0603]  (hidden comment: CRCW0603100RJNEA)
R105  ValueDisplayed: 22.0  [0603]  (hidden comment: RC0603FR-0722RL)
R106  ValueDisplayed: 10.0k  [0603]  (hidden comment: RMCF0603FT10K0)
R107  value 10k  [FP-RC0402JR-0710KL_0402-MFG]  (hidden comment: RC0402JR-0710KL)
R108  ValueDisplayed: 100  [0603]  (hidden comment: CRCW0603100RJNEA)
R109  ValueDisplayed: 10.0k  [0603]  (hidden comment: RMCF0603FT10K0)
R110  ValueDisplayed: 100  [0603]  (hidden comment: CRCW0603100RJNEA)
U20  TPS2HCS10-Q1  [PWP0016P-MFG]
U21  TPS2HCS10-Q1  [PWP0016P-MFG]
U22  TPS2HCS05A  [PWC0018A-MFG]

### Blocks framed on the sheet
TPS2HCS10-Q1: C58-C63 R80-R91 U20
TPS2HCS08-Q1: C64-C69 R92-R98 U21
TPS2HCS05-Q1: C70-C75 R99-R110 U22

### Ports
CS_TPS2HCS05 (in), CS_TPS2HCS10/08 (in), DI_TPS2HCS05 (in), DI_TPS2HCS08 (in), DI_TPS2HCS10 (in), FLT_TPS2HCS05 (out), FLT_TPS2HCS10/08 (out), LHI_TPS2HCS05 (in), LHI_TPS2HCS08 (in), LHI_TPS2HCS10 (in), SCLK_TPS2HCS05 (in), SCLK_TPS2HCS10/08 (in), SDI_TPS2HCS05 (in), SDI_TPS2HCS10/08 (in), SDO_TPS2HCS05 (out), SDO_TPS2HCS10/08 (out), SNS_TPS2HCS05 (out), SNS_TPS2HCS08 (out), SNS_TPS2HCS10 (out), VOUT1_TPS2HCS05 (out), VOUT1_TPS2HCS08 (out), VOUT1_TPS2HCS10 (out), VOUT2_TPS2HCS05 (out), VOUT2_TPS2HCS08 (out), VOUT2_TPS2HCS10 (out)

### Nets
3V3_1: R90.1 R107.1
3V3_ALWAYS_ON: R80.1 R81.2 R84.2 R92.1 R93.2 R100.1 R101.2 R106.2
12V_ALWAYS_ON: C60.1 C61.1 C66.1 C67.1 C74.1 C75.1 U20.17(VBB) U21.17(VBB) U22.1(VBB) U22.9(VBB) U22.10(VBB) U22.18(VBB) U22.19(VBB)
GND: C58.2 C59.2 C60.2 C61.2 C62.2 C63.2 C64.2 C65.2 C66.2 C67.2 C68.2 C69.2 C70.2 C71.2 C72.2 C73.2 C74.2 C75.2 R87.1 R96.1 R103.1 U20.1(GND) U21.1(GND) U22.2(GND)
ADC2_AIN0: C73.1 R103.2 U22.3(SNS) ; port SNS_TPS2HCS05
ADC2_AIN1: C63.1 R87.2 U20.2(SNS) ; port SNS_TPS2HCS10
ADC2_AIN2: C69.1 R96.2 U21.2(SNS) ; port SNS_TPS2HCS08
CS: R91.2 U20.15(~{CS}) U21.15(~{CS})  [project net CS_15]
CS_LD_1: R90.2 R91.1 ; port CS_TPS2HCS10/08
CS_LD_2: R107.2 R108.1 ; port CS_TPS2HCS05
DI_HCS: R81.1 R82.2 R93.1 R94.2 R106.1 R109.2 ; port DI_TPS2HCS10, port DI_TPS2HCS08, port DI_TPS2HCS05
FLT_TPS2HCS05: R102.2 ; port FLT_TPS2HCS05
FLT_TPS2HCS10/08: R86.1 ; port FLT_TPS2HCS10/08
FLT_TPS2HCS10/08: R84.1 R86.2 U20.12(FLT) U21.12(FLT)  [project net FLT_TPS2HCS10/08_15]  [a separate net that carries the same name]
LHI_HCS: R83.2 R95.2 R99.2 ; port LHI_TPS2HCS10, port LHI_TPS2HCS08, port LHI_TPS2HCS05
SCLK: R85.1 R110.1 ; port SCLK_TPS2HCS10/08, port SCLK_TPS2HCS05
SCLK: R85.2 U20.16(SCLK(DIAG_EN)) U21.16(SCLK(DIAG_EN))  [project net SCLK_15]  [a separate net that carries the same name]
SDI: R88.1 R104.1 ; port SDI_TPS2HCS10/08, port SDI_TPS2HCS05
SDI: R88.2 U20.13(SDI(EN2))  [project net SDI_15]  [a separate net that carries the same name]
SDO_LD: R98.1 R105.1 ; port SDO_TPS2HCS10/08, port SDO_TPS2HCS05
SDO_TPS2HCS10: R89.1 R97.1  [project net SDO_TPS2HCS10_15]
VOUT1_TPS2HCS05: C70.1 U22.7(VOUT1) U22.8(VOUT1) ; port VOUT1_TPS2HCS05
VOUT1_TPS2HCS08: C65.1 U21.6(VOUT1) U21.7(VOUT1) U21.8(VOUT1) ; port VOUT1_TPS2HCS08
VOUT1_TPS2HCS10: C59.1 U20.6(VOUT1) U20.7(VOUT1) U20.8(VOUT1) ; port VOUT1_TPS2HCS10
VOUT2_TPS2HCS05: C72.1 U22.11(VOUT2) U22.12(VOUT2) ; port VOUT2_TPS2HCS05
VOUT2_TPS2HCS08: C68.1 U21.9(VOUT2) U21.10(VOUT2) U21.11(VOUT2) ; port VOUT2_TPS2HCS08
VOUT2_TPS2HCS10: C62.1 U20.9(VOUT2) U20.10(VOUT2) U20.11(VOUT2) ; port VOUT2_TPS2HCS10
NetC58_1: C58.1 R80.2 U20.3(VDD)
NetC64_1: C64.1 R92.2 U21.3(VDD)
NetC71_1: C71.1 R100.2 U22.4(VDD)
NetR82_1: R82.1 U20.4(DI(EN1))
NetR83_1: R83.1 U20.5(LHI(ILIM))
NetR89_2: R89.2 U20.14(SDO(SEL))
NetR94_1: R94.1 U21.4(DI(EN1))
NetR95_1: R95.1 U21.5(LHI(ILIM))
NetR97_2: R97.2 U21.13(SDI(EN2))
NetR98_2: R98.2 U21.14(SDO(SEL))
NetR99_1: R99.1 U22.6(LHI)
NetR101_1: R101.1 R102.1 U22.13(~{FLT}/~{WAKE_SIG})
NetR104_2: R104.2 U22.14(SDI)
NetR105_2: R105.2 U22.15(SDO)
NetR108_2: R108.2 U22.16(~{CS})
NetR109_1: R109.1 U22.5(DI/OUT_DIS)
NetR110_2: R110.2 U22.17(SCLK)

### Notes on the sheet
- Daisy Chain TPS2HCS10 and TPS2HCS08
- If DI is set HI, CH1 and CH2 = ON in limp home state
- No RGND and DGND because there is upstream protection
- (near R86) Disable pullup resistor on TPLD!
- (near U20) Recommended to pull-up CS for AM263P
- Same package as TPS2HCS10
- (near U21) Daisy Chain TPS2HCS10 and TPS2HCS08
- Recommended to pull-up CS for AM263P

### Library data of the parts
C58 C64 C71 = CMP-0007050-1: CAP, CERM, 0.47 uF, 50 V, +/- 10%, X7R, 0603; Manufacturer: TDK; TaMin_C: -55°C; ESR_ohm: 10.974m; Polarized: N; SizeAreaWB_mm2: 4.68; Value1: 0.010974 ohm; U/M: EA; Value: 0.47uF; TaMax_C: 125°C; SizeZ_mm: 1; SizeX_mm: 1.6; SizeY_mm: 0.8; SizeArea_mm2: 1.28; IRMS_A: 1.5748A; AEC Category: Q200
C59 C62 C65 C68 C70 C72 = CMP-0007086-4: CAP, CERM, 0.022 uF, 100 V, +/- 10%, X7R, AEC-Q200 Grade 1, 0603; Manufacturer: TDK; TaMin_C: -55°C; ESR_ohm: 83.542m; Polarized: N; SizeAreaWB_mm2: 4.68; Value1: 0.083542 ohm; U/M: EA; TaMax_C: 125°C; SizeZ_mm: 1; SizeX_mm: 1.6; SizeY_mm: 0.8; SizeArea_mm2: 1.28; AEC Qualified: Y; IRMS_A: 609.312mA; AEC Category: Q200
C60 C66 C74 = CMP-0006356-2: CAP, CERM, 0.1 uF, 50 V, +/- 10%, X7R, AEC-Q200 Grade 1, 0402; Manufacturer: MuRata; TaMin_C: -55°C; Polarized: N; SizeAreaWB_mm2: 3; Value1: Unknown; U/M: EA; Value: 0.1uF; TaMax_C: 125°C; SizeZ_mm: 0.6; SizeX_mm: 1; SizeY_mm: 0.5; AEC Qualified: Y; Cap_F: 100nF; AEC Category: Q200
C61 C67 C75 = CMP-0006976-5: CAP, CERM, 1000 pF, 50 V, +/- 10%, X7R, 0603; Manufacturer: Kemet; TaMin_C: -55°C; Polarized: N; SizeAreaWB_mm2: 4.68; Value1: Unknown; U/M: EA; Value: 1000pF; TaMax_C: 125°C; SizeZ_mm: 1; SizeX_mm: 1.6; SizeY_mm: 0.8; SizeArea_mm2: 1.28; AEC Category: Q200
C63 C69 = CMP-0079247-1: CAP, CERM, 4700 pF, 100 V,+/- 10%, X7R, AEC-Q200 Grade 1, 0603; Manufacturer: MuRata; SizeAreaWB_mm2: 4.68; SizeArea_mm2: 1.28; AEC Qualified: Y; AEC Category: Q200; Value: 4700pF; TaMax_C: 125°C; SizeZ_mm: 1; Polarized: N; TaMin_C: -55°C; SizeY_mm: 0.8; U/M: EA; SizeX_mm: 1.6
C73 = CMP-0006847-3: CAP, CERM, 1000 pF, 50 V, +/- 10%, X7R, 0603; Manufacturer: Kemet; TaMin_C: -55°C; Polarized: N; SizeAreaWB_mm2: 4.68; Value1: Unknown; U/M: EA; Value: 1000pF; TaMax_C: 125°C; SizeZ_mm: 1; SizeX_mm: 1.6; SizeY_mm: 0.8; SizeArea_mm2: 1.28; AEC Category: Q200
R80 R92 R100 = CMP-0022004-4: RES, 10.0, 1%, 0.25 W, AEC-Q200 Grade 0, 0603; Manufacturer: Vishay-Dale; Power_W: 250mW; TempCo: 100 ppm/C; Value_Code: 10R0; Value: 10.0; EIA_Code: E96; Res_ohm: 10; SizeX_mm: 1.6; SizeY_mm: 0.8; SizeZ_mm: 1; Value2: 0.25W; SizeArea_mm2: 1.28; AEC Qualified: Y; VDC_V: 75V; AEC Category: Q200; AEC Grade: 0
R81-R84 R86 R93-R95 R99 R101 R102 R106 R109 = CMP-0023341-2: RES, 10.0 k, 1%, 0.1 W, AEC-Q200 Grade 0, 0603; Manufacturer: Stackpole Electronics Inc; Power_W: 100mW; TempCo: 100 ppm/C; Value_Code: 10k0; U/M: EA; Value: 10.0k; EIA_Code: E96; Res_ohm: 10k; SizeX_mm: 1.6; SizeY_mm: 0.8; SizeZ_mm: 1; Value2: 0.1W; SizeArea_mm2: 1.28; AEC Qualified: Y; VDC_V: 75V; AEC Grade: 0; AEC Category: Q200
R85 R88 R91 R97 R104 R108 R110 = CMP-0025700-3: RES, 100, 5%, 0.1 W, 0603; Manufacturer: Vishay-Dale; Power_W: 100mW; TempCo: 200 ppm/C; Value_Code: 100R; U/M: EA; Value: 100; EIA_Code: E24; SizeX_mm: 1.6; SizeY_mm: 0.8; SizeZ_mm: 1; Value2: 0.1W; SizeArea_mm2: 1.28; VDC_V: 75V; AEC Category: Q200
R87 R96 R103 = CMP-0022555-5: RES, 698, 1%, 0.1 W, AEC-Q200 Grade 0, 0603; Manufacturer: Vishay-Dale; Power_W: 100mW; TempCo: 100 ppm/C; Value_Code: 698R; Value: 698; EIA_Code: E96; SizeX_mm: 1.6; SizeY_mm: 0.8; SizeZ_mm: 1; Value2: 0.1W; SizeArea_mm2: 1.28; AEC Qualified: Y; VDC_V: 75V; AEC Category: Q200; AEC Grade: 0
R89 R105 = CMP-0022928-4: RES, 22.0, 1%, 0.1 W, 0603; Manufacturer: Yageo; Power_W: 100mW; TempCo: 100 ppm/C; Value_Code: 22R0; Value: 22.0; Res_ohm: 22; SizeX_mm: 1.6; SizeY_mm: 0.8; SizeZ_mm: 1; Value2: 0.1W; SizeArea_mm2: 1.28; AEC Qualified: N; VDC_V: 75V; AEC Category: Q200; SizeAreaWB_mm2: 4.68
R90 R107 = CMP-0094798-1: as R167 on sheet DRV8x45S-Q1 and DRV81242-Q1
R98 = CMP-0027500-1: as R170 on sheet DRV8x45S-Q1 and DRV81242-Q1
U20 U21 = CMP-0098417-1: Manufacturer: Texas Instruments; SizeZ_mm: 1.2mm; Standoff Height: 0.05mm
U22 = CMP-0124507-1: 5mΩ, Automotive Dual-Channel, SPI Controlled High-Side Switch with Integrated I2 t Wire Protection and low power mode; Manufacturer: Texas Instruments; SizeZ_mm: 1.2mm; AEC Qualified: Yes; AEC Grade: Grade 1; Max Supply Voltage: 18V; Min Supply Voltage: 6V; Nominal Supply Current: 2-4.9mA; Number Of Drivers: 2; Standoff Height: 0.05mm; TaMax_C: +125°C; TaMin_C: -40°C; TJmax_C: +150°C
